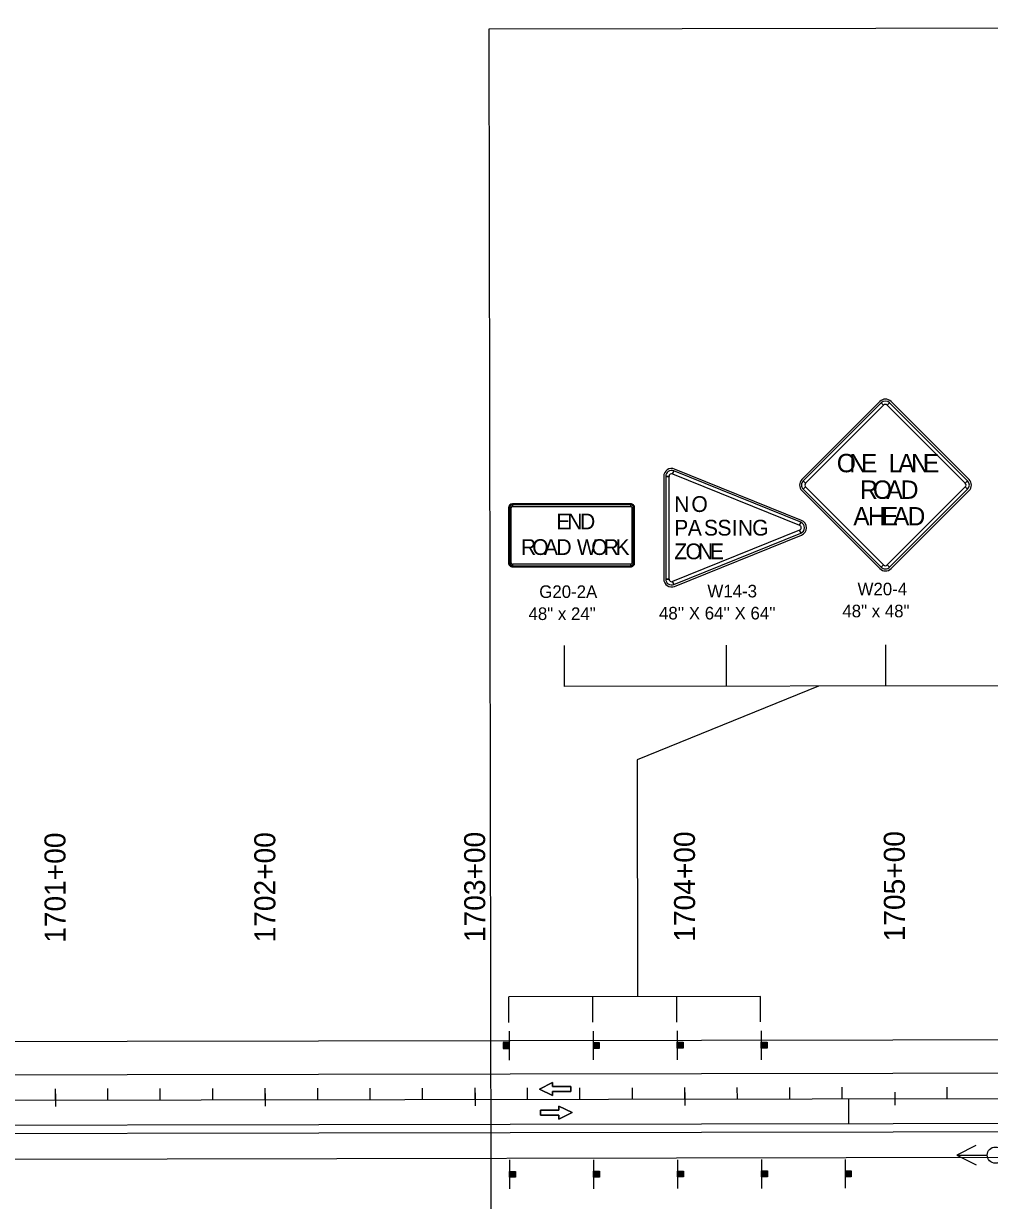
# Model space of a CAD drawing. Extents: x 16513048 to 16518780, y 7009856 to 7010869.
# Drawn here: x 16514826 to 16515286, y 7010308 to 7010869 of the extents above; entities that cross this region are included whole.
import ezdxf

# ---------------------------------------------------------------- set-up
doc = ezdxf.new("R2010")
doc.units = 0
for name, color, linetype in [('dsnNonPlotable', 7, 'Continuous'), ('dsnStdLabel', 7, 'Continuous'), ('Level 2', 7, 'Continuous'), ('Level 5', 7, 'Continuous'), ('NamedBoundary', 7, 'Continuous'), ('PavementMarking', 7, 'Continuous'), ('SheetBorder', 7, 'Continuous'), ('tdCoTitleBlock', 7, 'Continuous')]:
    doc.layers.add(name, color=color, linetype=linetype)

msp = doc.modelspace()

# ---------------------------------------------------------------- linework, layer by layer
at = {"layer": 'dsnNonPlotable'}
for p, q in [((16513050.27, 7010352.91), (16516699.62, 7010359.27)), ((16513050.32, 7010324.91), (16515740.86, 7010329.6))]:
    msp.add_line(p, q, dxfattribs=at)
for points in [[(16513050.22, 7010380.91), (16516699.59, 7010387.27), (16518770.65, 7010388.94)], [(16518770.66, 7010372.94), (16516699.61, 7010371.27), (16513050.25, 7010364.91)], [(16518770.68, 7010348.94), (16516699.64, 7010347.27), (16513050.29, 7010340.91)], [(16518770.69, 7010344.94), (16516699.64, 7010343.27), (16513050.3, 7010336.91)]]:
    msp.add_lwpolyline(points, dxfattribs=at)
at = {"layer": 'dsnStdLabel'}
for p, q in [((16515233.71, 7010689), (16515196.53, 7010651.83)), ((16515234.37, 7010688.34), (16515235.48, 7010687.23)), ((16515237.25, 7010687.23), (16515238.36, 7010688.34)), ((16515276.2, 7010651.83), (16515239.02, 7010689)), ((16515134.94, 7010654.48), (16515135.52, 7010655.93)), ((16515196.38, 7010632.32), (16515135.88, 7010656.8)), ((16515130.71, 7010653.32), (16515130.71, 7010604.37)), ((16515131.65, 7010653.32), (16515133.22, 7010653.32)), ((16515198.3, 7010650.06), (16515197.2, 7010651.16)), ((16515197.2, 7010647.18), (16515198.3, 7010648.29)), ((16515275.53, 7010651.16), (16515274.43, 7010650.06)), ((16515274.43, 7010648.29), (16515275.53, 7010647.18)), ((16515196.53, 7010646.52), (16515233.71, 7010609.34)), ((16515239.02, 7010609.34), (16515276.2, 7010646.52)), ((16515056.75, 7010638.39), (16515056.75, 7010612.11)), ((16515057.22, 7010638.39), (16515058, 7010638.39)), ((16515114.96, 7010640.27), (16515058.62, 7010640.27)), ((16515058.62, 7010639.02), (16515058.62, 7010639.8)), ((16515114.96, 7010639.8), (16515114.96, 7010639.02)), ((16515115.58, 7010638.39), (16515116.36, 7010638.39)), ((16515116.83, 7010612.11), (16515116.83, 7010638.39)), ((16515196.02, 7010631.45), (16515195.44, 7010630)), ((16515195.44, 7010627.68), (16515196.02, 7010626.23)), ((16515135.88, 7010600.89), (16515196.38, 7010625.36)), ((16515058, 7010612.11), (16515057.22, 7010612.11)), ((16515058.62, 7010610.7), (16515058.62, 7010611.48)), ((16515058.62, 7010610.23), (16515114.96, 7010610.23)), ((16515114.96, 7010611.48), (16515114.96, 7010610.7)), ((16515116.36, 7010612.11), (16515115.58, 7010612.11)), ((16515235.48, 7010611.11), (16515234.37, 7010610)), ((16515238.36, 7010610), (16515237.25, 7010611.11)), ((16515133.22, 7010604.37), (16515131.65, 7010604.37)), ((16515135.52, 7010601.76), (16515134.94, 7010603.21))]:
    msp.add_line(p, q, dxfattribs=at)
for points in [[(16515234.37, 7010688.34), (16515197.2, 7010651.16), (16515198.3, 7010650.06), (16515235.48, 7010687.23), (16515234.37, 7010688.34)], [(16515275.53, 7010651.16), (16515238.36, 7010688.34), (16515237.25, 7010687.23), (16515274.43, 7010650.06), (16515275.53, 7010651.16)], [(16515196.02, 7010631.45), (16515135.52, 7010655.93), (16515134.94, 7010654.48), (16515195.44, 7010630), (16515196.02, 7010631.45)], [(16515131.65, 7010653.32), (16515131.65, 7010604.37), (16515133.22, 7010604.37), (16515133.22, 7010653.32), (16515131.65, 7010653.32)], [(16515197.2, 7010647.18), (16515234.37, 7010610), (16515235.48, 7010611.11), (16515198.3, 7010648.29), (16515197.2, 7010647.18)], [(16515238.36, 7010610), (16515275.53, 7010647.18), (16515274.43, 7010648.29), (16515237.25, 7010611.11), (16515238.36, 7010610)], [(16515057.22, 7010638.39), (16515057.22, 7010612.11), (16515058, 7010612.11), (16515058, 7010638.39), (16515057.22, 7010638.39)], [(16515114.96, 7010639.8), (16515058.62, 7010639.8), (16515058.62, 7010639.02), (16515114.96, 7010639.02), (16515114.96, 7010639.8)], [(16515116.36, 7010612.11), (16515116.36, 7010638.39), (16515115.58, 7010638.39), (16515115.58, 7010612.11), (16515116.36, 7010612.11)], [(16515135.52, 7010601.76), (16515196.02, 7010626.23), (16515195.44, 7010627.68), (16515134.94, 7010603.21), (16515135.52, 7010601.76)], [(16515058.62, 7010610.7), (16515114.96, 7010610.7), (16515114.96, 7010611.48), (16515058.62, 7010611.48), (16515058.62, 7010610.7)]]:
    msp.add_lwpolyline(points, close=True, dxfattribs=at)
for centre, radius, start, end in [((16515236.37, 7010686.35), 3.76, 45, 134.9997), ((16515236.37, 7010686.35), 2.82, 45, 134.9997), ((16515236.37, 7010686.35), 1.25, 45, 134.9997), ((16515134.47, 7010653.32), 3.76, 67.9757, 179.9998), ((16515134.47, 7010653.32), 2.82, 67.9757, 179.9998), ((16515134.47, 7010653.32), 1.25, 67.9757, 179.9998), ((16515199.19, 7010649.17), 3.76, 134.9997, 225), ((16515199.19, 7010649.17), 2.82, 134.9997, 225), ((16515199.19, 7010649.17), 1.25, 134.9997, 225), ((16515273.54, 7010649.17), 1.25, 315.0002, 44.9998), ((16515273.54, 7010649.17), 2.82, 315.0002, 44.9998), ((16515273.54, 7010649.17), 3.76, 315.0002, 44.9998), ((16515058.62, 7010638.39), 1.88, 90.0002, 179.9998), ((16515058.62, 7010638.39), 1.41, 90.0002, 179.9998), ((16515058.62, 7010638.39), 0.626, 90.0002, 179.9998), ((16515114.96, 7010638.39), 1.88, 0, 90.0002), ((16515114.96, 7010638.39), 1.41, 0, 90.0002), ((16515114.96, 7010638.39), 0.626, 0, 90.0002), ((16515194.97, 7010628.84), 2.82, 292.0246, 67.9754), ((16515194.97, 7010628.84), 3.76, 292.0246, 67.976), ((16515194.97, 7010628.84), 1.25, 292.0246, 67.9754), ((16515058.62, 7010612.11), 1.88, 179.9998, 270.0001), ((16515058.62, 7010612.11), 1.41, 179.9998, 270.0001), ((16515058.62, 7010612.11), 0.626, 179.9998, 270.0001), ((16515114.96, 7010612.11), 1.88, 270.0001, 0.0003), ((16515114.96, 7010612.11), 1.41, 270.0001, 0.0003), ((16515114.96, 7010612.11), 0.626, 270.0001, 0.0003), ((16515236.37, 7010612), 3.76, 225, 315.0002), ((16515236.37, 7010612), 2.82, 225, 315.0002), ((16515236.37, 7010612), 1.25, 225, 315.0002), ((16515134.47, 7010604.37), 3.76, 179.9998, 292.0246), ((16515134.47, 7010604.37), 2.82, 179.9998, 292.0246), ((16515134.47, 7010604.37), 1.25, 179.9998, 292.0246)]:
    msp.add_arc(centre, radius, start, end, dxfattribs=at)
at = {"layer": 'Level 2'}
for p, q in [((16515083.24, 7010572.74), (16515083.27, 7010553.13)), ((16515160.42, 7010572.87), (16515160.45, 7010553.27)), ((16515236.42, 7010573), (16515236.45, 7010553.4)), ((16515325.77, 7010553.56), (16515083.27, 7010553.13)), ((16515204.52, 7010553.35), (16515118.04, 7010518.29)), ((16515118.04, 7010518.29), (16515118.23, 7010405.32)), ((16515176.88, 7010405.42), (16515056.88, 7010405.22)), ((16515056.9, 7010393.07), (16515056.88, 7010405.22)), ((16515096.9, 7010393.14), (16515096.88, 7010405.29)), ((16515136.9, 7010393.21), (16515136.88, 7010405.36)), ((16515176.9, 7010393.28), (16515176.88, 7010405.42)), ((16515057.11, 7010388.88), (16515057.11, 7010375.11)), ((16515097.11, 7010388.95), (16515097.11, 7010375.18)), ((16515137.11, 7010389.02), (16515137.11, 7010375.25)), ((16515177.11, 7010389.09), (16515177.11, 7010375.32)), ((16515054.44, 7010383.44), (16515054.44, 7010380.64)), ((16515054.6, 7010380.64), (16515054.6, 7010383.44)), ((16515054.72, 7010383.44), (16515054.72, 7010380.64)), ((16515054.88, 7010380.64), (16515054.88, 7010383.44)), ((16515054.99, 7010383.44), (16515054.98, 7010380.64)), ((16515055.2, 7010380.64), (16515055.2, 7010383.44)), ((16515055.31, 7010383.44), (16515055.31, 7010380.64)), ((16515055.52, 7010380.64), (16515055.52, 7010383.44)), ((16515055.71, 7010383.44), (16515055.71, 7010380.64)), ((16515055.87, 7010380.64), (16515055.88, 7010383.44)), ((16515055.98, 7010383.44), (16515055.98, 7010380.64)), ((16515056.12, 7010380.64), (16515056.12, 7010383.44)), ((16515056.28, 7010383.44), (16515056.28, 7010380.64)), ((16515056.39, 7010380.64), (16515056.39, 7010383.44)), ((16515056.5, 7010383.44), (16515056.5, 7010380.64)), ((16515056.63, 7010380.64), (16515056.63, 7010383.44)), ((16515056.76, 7010383.44), (16515056.76, 7010380.64)), ((16515056.9, 7010380.64), (16515056.9, 7010383.44)), ((16515097.32, 7010380.71), (16515097.32, 7010383.51)), ((16515097.46, 7010383.51), (16515097.46, 7010380.71)), ((16515097.59, 7010380.71), (16515097.59, 7010383.51)), ((16515097.72, 7010383.51), (16515097.72, 7010380.71)), ((16515097.83, 7010380.71), (16515097.83, 7010383.51)), ((16515097.94, 7010383.51), (16515097.94, 7010380.71)), ((16515098.11, 7010380.71), (16515098.11, 7010383.51)), ((16515098.24, 7010383.51), (16515098.24, 7010380.71)), ((16515098.35, 7010380.71), (16515098.34, 7010383.51)), ((16515098.51, 7010383.51), (16515098.51, 7010380.71)), ((16515098.7, 7010380.71), (16515098.7, 7010383.51)), ((16515098.91, 7010383.51), (16515098.91, 7010380.71)), ((16515099.03, 7010380.71), (16515099.02, 7010383.51)), ((16515099.23, 7010383.51), (16515099.24, 7010380.71)), ((16515099.35, 7010380.71), (16515099.35, 7010383.51)), ((16515099.51, 7010383.51), (16515099.51, 7010380.71)), ((16515099.62, 7010380.71), (16515099.62, 7010383.51)), ((16515099.78, 7010383.51), (16515099.78, 7010380.71)), ((16515137.32, 7010380.78), (16515137.32, 7010383.58)), ((16515137.46, 7010383.58), (16515137.46, 7010380.78)), ((16515137.59, 7010380.78), (16515137.59, 7010383.58)), ((16515137.72, 7010383.58), (16515137.72, 7010380.78)), ((16515137.83, 7010380.78), (16515137.83, 7010383.58)), ((16515137.94, 7010383.58), (16515137.94, 7010380.78)), ((16515138.11, 7010380.78), (16515138.11, 7010383.58)), ((16515138.24, 7010383.58), (16515138.24, 7010380.78)), ((16515138.35, 7010380.78), (16515138.34, 7010383.58)), ((16515138.51, 7010383.58), (16515138.51, 7010380.78)), ((16515138.7, 7010380.78), (16515138.7, 7010383.58)), ((16515138.91, 7010383.58), (16515138.91, 7010380.78)), ((16515139.03, 7010380.78), (16515139.02, 7010383.58)), ((16515139.23, 7010383.58), (16515139.24, 7010380.78)), ((16515139.35, 7010380.78), (16515139.35, 7010383.58)), ((16515139.51, 7010383.58), (16515139.51, 7010380.78)), ((16515139.62, 7010380.78), (16515139.62, 7010383.58)), ((16515139.78, 7010383.58), (16515139.78, 7010380.78)), ((16515177.32, 7010380.85), (16515177.32, 7010383.65)), ((16515177.46, 7010383.65), (16515177.46, 7010380.85)), ((16515177.59, 7010380.85), (16515177.59, 7010383.65)), ((16515177.72, 7010383.65), (16515177.72, 7010380.85)), ((16515177.83, 7010380.85), (16515177.83, 7010383.65)), ((16515177.94, 7010383.65), (16515177.94, 7010380.85)), ((16515178.11, 7010380.85), (16515178.11, 7010383.65)), ((16515178.24, 7010383.65), (16515178.24, 7010380.85)), ((16515178.35, 7010380.85), (16515178.34, 7010383.65)), ((16515178.51, 7010383.65), (16515178.51, 7010380.85)), ((16515178.7, 7010380.85), (16515178.7, 7010383.65)), ((16515178.91, 7010383.65), (16515178.91, 7010380.85)), ((16515179.03, 7010380.85), (16515179.02, 7010383.65)), ((16515179.23, 7010383.65), (16515179.24, 7010380.85)), ((16515179.35, 7010380.85), (16515179.35, 7010383.65)), ((16515179.51, 7010383.65), (16515179.51, 7010380.85)), ((16515179.62, 7010380.85), (16515179.62, 7010383.65)), ((16515179.78, 7010383.65), (16515179.78, 7010380.85)), ((16515279.52, 7010334.39), (16515270.39, 7010329.8)), ((16515270.39, 7010329.8), (16515284.89, 7010329.83)), ((16515270.39, 7010329.8), (16515279.54, 7010325.24)), ((16515057.22, 7010327.51), (16515057.22, 7010313.74)), ((16515097.22, 7010327.58), (16515097.22, 7010313.81)), ((16515137.22, 7010327.65), (16515137.22, 7010313.88)), ((16515177.22, 7010327.72), (16515177.22, 7010313.95)), ((16515217.22, 7010327.79), (16515217.22, 7010314.02)), ((16515057.42, 7010319.27), (16515057.42, 7010322.07)), ((16515057.57, 7010322.07), (16515057.57, 7010319.27)), ((16515057.7, 7010319.27), (16515057.7, 7010322.07)), ((16515057.83, 7010322.07), (16515057.83, 7010319.27)), ((16515057.94, 7010319.27), (16515057.94, 7010322.07)), ((16515058.04, 7010322.07), (16515058.04, 7010319.27)), ((16515058.21, 7010319.27), (16515058.21, 7010322.07)), ((16515058.35, 7010322.07), (16515058.35, 7010319.27)), ((16515058.46, 7010319.27), (16515058.45, 7010322.07)), ((16515058.62, 7010322.07), (16515058.62, 7010319.27)), ((16515058.81, 7010319.27), (16515058.81, 7010322.07)), ((16515059.02, 7010322.07), (16515059.02, 7010319.27)), ((16515059.13, 7010319.27), (16515059.12, 7010322.07)), ((16515059.34, 7010322.07), (16515059.35, 7010319.27)), ((16515059.45, 7010319.27), (16515059.45, 7010322.07)), ((16515059.61, 7010322.07), (16515059.61, 7010319.27)), ((16515059.73, 7010319.27), (16515059.73, 7010322.07)), ((16515059.88, 7010322.07), (16515059.88, 7010319.27)), ((16515097.42, 7010319.34), (16515097.42, 7010322.14)), ((16515097.57, 7010322.14), (16515097.57, 7010319.34)), ((16515097.7, 7010319.34), (16515097.7, 7010322.14)), ((16515097.83, 7010322.14), (16515097.83, 7010319.34)), ((16515097.94, 7010319.34), (16515097.94, 7010322.14)), ((16515098.04, 7010322.14), (16515098.04, 7010319.34)), ((16515098.21, 7010319.34), (16515098.21, 7010322.14)), ((16515098.35, 7010322.14), (16515098.35, 7010319.34)), ((16515098.46, 7010319.34), (16515098.45, 7010322.14)), ((16515098.62, 7010322.14), (16515098.62, 7010319.34)), ((16515098.81, 7010319.34), (16515098.81, 7010322.14)), ((16515099.02, 7010322.14), (16515099.02, 7010319.34)), ((16515099.13, 7010319.34), (16515099.12, 7010322.14)), ((16515099.34, 7010322.14), (16515099.35, 7010319.34)), ((16515099.45, 7010319.34), (16515099.45, 7010322.14)), ((16515099.61, 7010322.14), (16515099.61, 7010319.34)), ((16515099.73, 7010319.34), (16515099.73, 7010322.14)), ((16515099.88, 7010322.14), (16515099.88, 7010319.34)), ((16515137.42, 7010319.41), (16515137.42, 7010322.21)), ((16515137.57, 7010322.21), (16515137.57, 7010319.41)), ((16515137.7, 7010319.41), (16515137.7, 7010322.21)), ((16515137.83, 7010322.21), (16515137.83, 7010319.41)), ((16515137.94, 7010319.41), (16515137.94, 7010322.21)), ((16515138.04, 7010322.21), (16515138.04, 7010319.41)), ((16515138.21, 7010319.41), (16515138.21, 7010322.21)), ((16515138.35, 7010322.21), (16515138.35, 7010319.41)), ((16515138.46, 7010319.41), (16515138.45, 7010322.21)), ((16515138.62, 7010322.21), (16515138.62, 7010319.41)), ((16515138.81, 7010319.41), (16515138.81, 7010322.21)), ((16515139.02, 7010322.21), (16515139.02, 7010319.41)), ((16515139.13, 7010319.41), (16515139.12, 7010322.21)), ((16515139.34, 7010322.21), (16515139.35, 7010319.41)), ((16515139.45, 7010319.41), (16515139.45, 7010322.21)), ((16515139.61, 7010322.21), (16515139.61, 7010319.41)), ((16515139.73, 7010319.41), (16515139.73, 7010322.21)), ((16515139.88, 7010322.21), (16515139.88, 7010319.41)), ((16515177.42, 7010319.48), (16515177.42, 7010322.28)), ((16515177.57, 7010322.28), (16515177.57, 7010319.48)), ((16515177.7, 7010319.48), (16515177.7, 7010322.28)), ((16515177.83, 7010322.28), (16515177.83, 7010319.48)), ((16515177.94, 7010319.48), (16515177.94, 7010322.28)), ((16515178.04, 7010322.28), (16515178.04, 7010319.48)), ((16515178.21, 7010319.48), (16515178.21, 7010322.28)), ((16515178.34, 7010322.28), (16515178.34, 7010319.48)), ((16515178.46, 7010319.48), (16515178.45, 7010322.28)), ((16515178.62, 7010322.28), (16515178.62, 7010319.48)), ((16515178.81, 7010319.48), (16515178.81, 7010322.28)), ((16515179.02, 7010322.28), (16515179.02, 7010319.48)), ((16515179.13, 7010319.48), (16515179.12, 7010322.28)), ((16515179.34, 7010322.28), (16515179.35, 7010319.48)), ((16515179.45, 7010319.48), (16515179.45, 7010322.28)), ((16515179.61, 7010322.28), (16515179.61, 7010319.48)), ((16515179.72, 7010319.48), (16515179.72, 7010322.28)), ((16515179.88, 7010322.28), (16515179.88, 7010319.48)), ((16515217.42, 7010319.55), (16515217.42, 7010322.35)), ((16515217.57, 7010322.35), (16515217.57, 7010319.55)), ((16515217.7, 7010319.55), (16515217.7, 7010322.35)), ((16515217.83, 7010322.35), (16515217.83, 7010319.55)), ((16515217.94, 7010319.55), (16515217.94, 7010322.35)), ((16515218.04, 7010322.35), (16515218.04, 7010319.55)), ((16515218.21, 7010319.55), (16515218.21, 7010322.35)), ((16515218.34, 7010322.35), (16515218.34, 7010319.55)), ((16515218.46, 7010319.55), (16515218.45, 7010322.35)), ((16515218.62, 7010322.35), (16515218.62, 7010319.55)), ((16515218.81, 7010319.55), (16515218.81, 7010322.35)), ((16515219.02, 7010322.35), (16515219.02, 7010319.55)), ((16515219.13, 7010319.55), (16515219.12, 7010322.35)), ((16515219.34, 7010322.35), (16515219.35, 7010319.55)), ((16515219.45, 7010319.55), (16515219.45, 7010322.35)), ((16515219.61, 7010322.35), (16515219.61, 7010319.55)), ((16515219.72, 7010319.55), (16515219.72, 7010322.35)), ((16515219.88, 7010322.35), (16515219.88, 7010319.55))]:
    msp.add_line(p, q, dxfattribs=at)
for points in [[(16515057.06, 7010380.64), (16515057.06, 7010383.46), (16515054.25, 7010383.46), (16515054.25, 7010380.64)], [(16515097.16, 7010380.71), (16515097.16, 7010383.53), (16515099.98, 7010383.53), (16515099.98, 7010380.71)], [(16515137.16, 7010380.78), (16515137.16, 7010383.6), (16515139.98, 7010383.6), (16515139.98, 7010380.78)], [(16515177.16, 7010380.85), (16515177.16, 7010383.67), (16515179.98, 7010383.67), (16515179.98, 7010380.85)], [(16515086.47, 7010362.6), (16515086.48, 7010360.1), (16515077.73, 7010360.08), (16515077.73, 7010358.21), (16515071.47, 7010361.32), (16515077.72, 7010364.46), (16515077.72, 7010362.58)], [(16515072.04, 7010348.81), (16515072.03, 7010351.31), (16515080.78, 7010351.32), (16515080.78, 7010353.19), (16515087.03, 7010350.08), (16515080.79, 7010346.94), (16515080.79, 7010348.82)], [(16515057.27, 7010319.27), (16515057.27, 7010322.09), (16515060.08, 7010322.09), (16515060.08, 7010319.27)], [(16515097.27, 7010319.34), (16515097.27, 7010322.16), (16515100.08, 7010322.16), (16515100.08, 7010319.34)], [(16515137.27, 7010319.41), (16515137.27, 7010322.23), (16515140.08, 7010322.23), (16515140.08, 7010319.41)], [(16515177.27, 7010319.48), (16515177.27, 7010322.3), (16515180.08, 7010322.3), (16515180.08, 7010319.48)], [(16515217.27, 7010319.55), (16515217.27, 7010322.37), (16515220.08, 7010322.37), (16515220.08, 7010319.55)]]:
    msp.add_lwpolyline(points, close=True, dxfattribs=at)
msp.add_circle((16515288.76, 7010329.83), 3.87, dxfattribs=at)
at = {"layer": 'Level 5'}
for points in [[(16515077.72, 7010362.58), (16515077.72, 7010364.46), (16515071.47, 7010361.32), (16515077.73, 7010358.21), (16515077.73, 7010360.08), (16515086.48, 7010360.1), (16515086.47, 7010362.6), (16515077.72, 7010362.58)], [(16515080.79, 7010348.82), (16515080.79, 7010346.94), (16515087.03, 7010350.08), (16515080.78, 7010353.19), (16515080.78, 7010351.32), (16515072.03, 7010351.31), (16515072.04, 7010348.81), (16515080.79, 7010348.82)]]:
    msp.add_lwpolyline(points, dxfattribs=at)
at = {"layer": 'NamedBoundary'}
msp.add_lwpolyline([(16515047.4, 7010866.4), (16515049.16, 7009856.4), (16516616.66, 7009859.13), (16516614.9, 7010869.13)], close=True, dxfattribs=at)
at = {"layer": 'PavementMarking'}
msp.add_line((16515218.72, 7010356.69), (16515218.74, 7010344.69), dxfattribs=at)
at = {"layer": 'SheetBorder'}
for p, q in [((16515165.79, 7010356.6), (16515165.78, 7010362.06)), ((16515190.79, 7010356.64), (16515190.78, 7010362.1)), ((16515215.79, 7010356.69), (16515215.78, 7010362.15)), ((16515265.79, 7010356.78), (16515265.78, 7010362.24)), ((16514840.79, 7010359.09), (16514840.8, 7010352.97)), ((16514865.79, 7010356.08), (16514865.78, 7010361.54)), ((16514890.79, 7010356.12), (16514890.78, 7010361.58)), ((16514915.79, 7010356.16), (16514915.78, 7010361.62)), ((16514940.79, 7010359.27), (16514940.8, 7010353.15)), ((16514965.79, 7010356.25), (16514965.78, 7010361.71)), ((16514990.79, 7010356.3), (16514990.78, 7010361.76)), ((16515015.79, 7010356.34), (16515015.78, 7010361.8)), ((16515040.79, 7010359.44), (16515040.8, 7010353.32)), ((16515065.79, 7010356.43), (16515065.78, 7010361.89)), ((16515090.79, 7010356.47), (16515090.78, 7010361.93)), ((16515115.79, 7010356.51), (16515115.78, 7010361.97)), ((16515140.79, 7010359.62), (16515140.8, 7010353.5)), ((16515240.79, 7010359.79), (16515240.8, 7010353.67))]:
    msp.add_line(p, q, dxfattribs=at)
at = {"layer": 'tdCoTitleBlock'}
for p, q in [((16514840.79, 7010356.03), (16514840.78, 7010361.49)), ((16514940.79, 7010356.21), (16514940.78, 7010361.67)), ((16515040.79, 7010356.38), (16515040.78, 7010361.84)), ((16515140.79, 7010356.56), (16515140.78, 7010362.02)), ((16515240.79, 7010359.79), (16515240.8, 7010353.67))]:
    msp.add_line(p, q, dxfattribs=at)

# ---------------------------------------------------------------- texts
at = {"layer": 'dsnStdLabel'}
for s, height, p in [('O', 8.76, (16515213.19, 7010655.27)), ('N', 8.76, (16515219.09, 7010655.27)), ('E', 8.76, (16515224.71, 7010655.27)), ('L', 8.76, (16515237.85, 7010655.27)), ('A', 8.76, (16515242.46, 7010655.27)), ('N', 8.76, (16515248.6, 7010655.27)), ('E', 8.76, (16515254.22, 7010655.27)), ('R', 8.76, (16515224.26, 7010642.6)), ('O', 8.76, (16515230.41, 7010642.6)), ('A', 8.76, (16515236.84, 7010642.6)), ('D', 8.76, (16515243.68, 7010642.6)), ('N', 7.51, (16515135.7, 7010636.35)), ('O', 7.51, (16515143.89, 7010636.35)), ('A', 8.76, (16515221.04, 7010629.93)), ('H', 8.76, (16515227.98, 7010629.93)), ('E', 8.76, (16515234.6, 7010629.93)), ('A', 8.76, (16515239.96, 7010629.93)), ('D', 8.76, (16515246.9, 7010629.93)), ('E', 7.51, (16515079.44, 7010628.07)), ('N', 7.51, (16515084.76, 7010628.07)), ('D', 7.51, (16515090.81, 7010628.07)), ('P', 7.51, (16515135.7, 7010625.09)), ('A', 7.51, (16515142.16, 7010625.09)), ('S', 7.51, (16515149.85, 7010625.09)), ('S', 7.51, (16515156.3, 7010625.09)), ('I', 7.51, (16515163.11, 7010625.09)), ('N', 7.51, (16515166.04, 7010625.09)), ('G', 7.51, (16515172.85, 7010625.09)), ('R', 7.51, (16515062.69, 7010615.86)), ('O', 7.51, (16515068.04, 7010615.86)), ('A', 7.51, (16515073.62, 7010615.86)), ('D', 7.51, (16515079.56, 7010615.86)), ('W', 7.51, (16515089.3, 7010615.86)), ('O', 7.51, (16515096.18, 7010615.86)), ('R', 7.51, (16515102.07, 7010615.86)), ('K', 7.51, (16515107.72, 7010615.86)), ('Z', 7.51, (16515135.7, 7010613.82)), ('O', 7.51, (16515141.08, 7010613.82)), ('N', 7.51, (16515147, 7010613.82)), ('E', 7.51, (16515152.69, 7010613.82)), ('G20-2A', 6, (16515071.38, 7010595.36)), ('W14-3', 6, (16515151.52, 7010595.63)), ('W20-4', 6, (16515223.08, 7010596.64)), ('48" x 48"', 6, (16515215.83, 7010586.14)), ('48" x 24"', 6, (16515066.26, 7010584.86)), ("48'' X 64'' X 64''", 6, (16515128.45, 7010585.13))]:
    msp.add_text(s, height=height, dxfattribs=at).set_placement(p)
at = {"layer": 'SheetBorder'}
for s, p in [('1701+00', (16514845.67, 7010431.04)), ('1702+00', (16514945.67, 7010431.22)), ('1703+00', (16515045.67, 7010431.39)), ('1704+00', (16515145.67, 7010431.57)), ('1705+00', (16515245.67, 7010431.74))]:
    msp.add_text(s, height=10.02, rotation=90.0999, dxfattribs=at).set_placement(p)
at = {"layer": 'tdCoTitleBlock'}
msp.add_text('1705+00', height=10.02, rotation=90.0999, dxfattribs=at).set_placement((16515245.67, 7010431.74))

doc.saveas('drawing.dxf')
